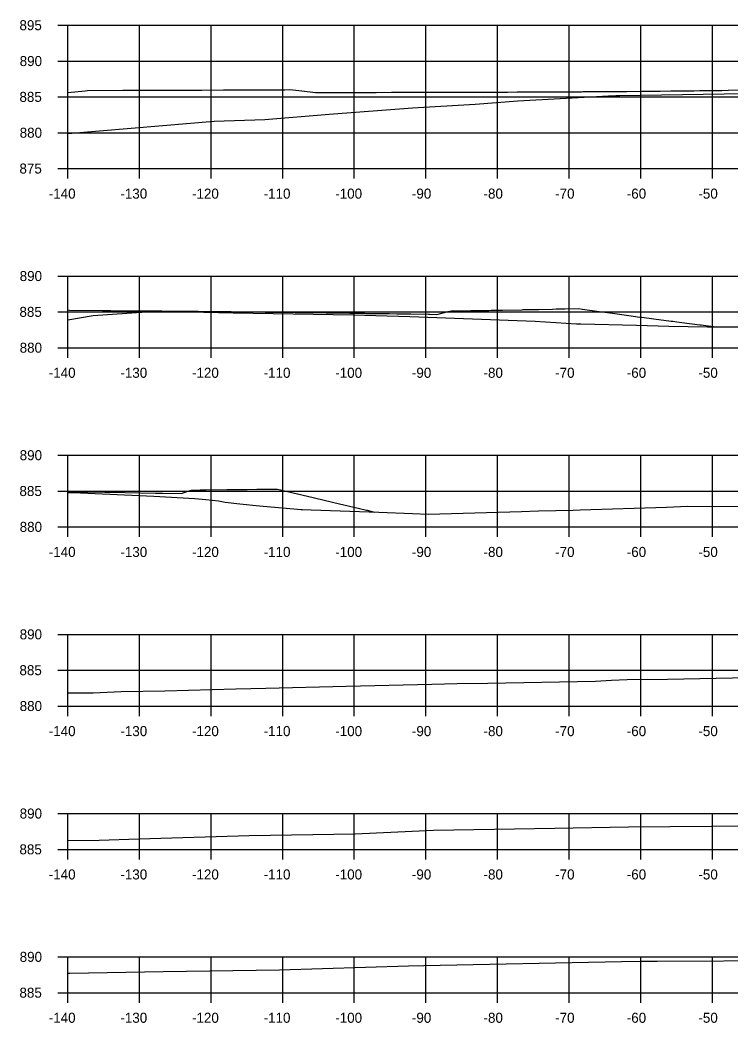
# Model space of a CAD drawing. Extents: x 1098669 to 1198896, y 698679 to 704410.
# Drawn here: x 1110634.5 to 1110733.7, y 701504.9 to 701644.8 of the extents above; entities that cross this region are included whole.
import ezdxf

# ---------------------------------------------------------------- set-up
doc = ezdxf.new("R2010")
doc.units = 0
for name, color, linetype in [('Proposed Surface', 7, 'Continuous'), ('R_Axis', 7, 'Continuous'), ('R_Axis Annot', 7, 'Continuous'), ('R_Fin Surface', 7, 'Continuous'), ('R_Grid', 7, 'Continuous')]:
    doc.layers.add(name, color=color, linetype=linetype)

msp = doc.modelspace()

# ---------------------------------------------------------------- linework, layer by layer
at = {"layer": 'Proposed Surface'}
for points in [[(1110641.16, 701629), (1110654.45, 701630.12), (1110661.6, 701630.72), (1110668.68, 701630.97), (1110677.65, 701631.7), (1110689.27, 701632.59), (1110698.01, 701633.13), (1110703.97, 701633.57), (1110716.65, 701634.28), (1110717.65, 701634.31), (1110718.25, 701634.32), (1110732.78, 701634.57), (1110735.56, 701634.61)], [(1110641.16, 701603), (1110644.68, 701603.63), (1110650.75, 701604.02), (1110652.23, 701604.13), (1110654.28, 701604.13), (1110658.11, 701604.13), (1110664.23, 701603.99), (1110681.01, 701603.73), (1110688.9, 701603.47), (1110706.39, 701602.82), (1110712.18, 701602.47), (1110712.61, 701602.46), (1110712.8, 701602.45), (1110720.56, 701602.28), (1110725.07, 701602.12), (1110730.48, 701602.06), (1110735.69, 701602.04)], [(1110641.16, 701578.92), (1110641.93, 701578.91), (1110653.19, 701578.39), (1110658.89, 701578.1), (1110660.41, 701577.95), (1110662.19, 701577.78), (1110663.15, 701577.57), (1110665.18, 701577.35), (1110667.93, 701577.08), (1110673.23, 701576.61), (1110673.75, 701576.56), (1110673.94, 701576.54), (1110675.13, 701576.5), (1110684.6, 701576.18), (1110689.29, 701576), (1110691.47, 701575.91), (1110704.51, 701576.28), (1110706.89, 701576.36), (1110711.72, 701576.47), (1110712.68, 701576.52), (1110724.75, 701576.87), (1110727.68, 701577.01), (1110734.95, 701576.99)], [(1110641.16, 701550.96), (1110644.68, 701550.98), (1110648.59, 701551.14), (1110654.71, 701551.25), (1110664.63, 701551.51), (1110668.83, 701551.61), (1110680.01, 701551.89), (1110691.99, 701552.16), (1110695.53, 701552.25), (1110699.79, 701552.34), (1110714.81, 701552.62), (1110717.08, 701552.73), (1110719.23, 701552.83), (1110724.88, 701552.88), (1110756.59, 701553.51)], [(1110641.16, 701530.35), (1110645.55, 701530.42), (1110651.09, 701530.58), (1110666.49, 701531.04), (1110681.3, 701531.28), (1110692.21, 701531.8), (1110709.14, 701532.09), (1110719.46, 701532.28), (1110754.17, 701532.55)], [(1110641.16, 701511.83), (1110641.46, 701511.83), (1110654.46, 701512.1), (1110670.71, 701512.33), (1110688.72, 701512.87), (1110690.88, 701512.93), (1110718.45, 701513.47), (1110721.18, 701513.52), (1110723.44, 701513.53), (1110760.56, 701513.71)]]:
    msp.add_lwpolyline(points, dxfattribs=at)
at = {"layer": 'R_Axis'}
for p, q in [((1110639.76, 701644.13), (1110641.16, 701644.13)), ((1110641.16, 701624.13), (1110641.16, 701644.13)), ((1110639.76, 701639.13), (1110641.16, 701639.13)), ((1110639.76, 701634.13), (1110641.16, 701634.13)), ((1110639.76, 701629.13), (1110641.16, 701629.13)), ((1110639.76, 701624.13), (1110641.16, 701624.13)), ((1110641.16, 701624.13), (1110921.16, 701624.13)), ((1110641.16, 701622.73), (1110641.16, 701624.13)), ((1110651.16, 701622.73), (1110651.16, 701624.13)), ((1110661.16, 701622.73), (1110661.16, 701624.13)), ((1110671.16, 701622.73), (1110671.16, 701624.13)), ((1110681.16, 701622.73), (1110681.16, 701624.13)), ((1110691.16, 701622.73), (1110691.16, 701624.13)), ((1110701.16, 701622.73), (1110701.16, 701624.13)), ((1110711.16, 701622.73), (1110711.16, 701624.13)), ((1110721.16, 701622.73), (1110721.16, 701624.13)), ((1110731.16, 701622.73), (1110731.16, 701624.13)), ((1110639.76, 701609.13), (1110641.16, 701609.13)), ((1110641.16, 701599.13), (1110641.16, 701609.13)), ((1110639.76, 701604.13), (1110641.16, 701604.13)), ((1110639.76, 701599.13), (1110641.16, 701599.13)), ((1110641.16, 701599.13), (1110921.16, 701599.13)), ((1110641.16, 701597.73), (1110641.16, 701599.13)), ((1110651.16, 701597.73), (1110651.16, 701599.13)), ((1110661.16, 701597.73), (1110661.16, 701599.13)), ((1110671.16, 701597.73), (1110671.16, 701599.13)), ((1110681.16, 701597.73), (1110681.16, 701599.13)), ((1110691.16, 701597.73), (1110691.16, 701599.13)), ((1110701.16, 701597.73), (1110701.16, 701599.13)), ((1110711.16, 701597.73), (1110711.16, 701599.13)), ((1110721.16, 701597.73), (1110721.16, 701599.13)), ((1110731.16, 701597.73), (1110731.16, 701599.13)), ((1110639.76, 701584.13), (1110641.16, 701584.13)), ((1110641.16, 701574.13), (1110641.16, 701584.13)), ((1110639.76, 701579.13), (1110641.16, 701579.13)), ((1110639.76, 701574.13), (1110641.16, 701574.13)), ((1110641.16, 701574.13), (1110921.16, 701574.13)), ((1110641.16, 701572.73), (1110641.16, 701574.13)), ((1110651.16, 701572.73), (1110651.16, 701574.13)), ((1110661.16, 701572.73), (1110661.16, 701574.13)), ((1110671.16, 701572.73), (1110671.16, 701574.13)), ((1110681.16, 701572.73), (1110681.16, 701574.13)), ((1110691.16, 701572.73), (1110691.16, 701574.13)), ((1110701.16, 701572.73), (1110701.16, 701574.13)), ((1110711.16, 701572.73), (1110711.16, 701574.13)), ((1110721.16, 701572.73), (1110721.16, 701574.13)), ((1110731.16, 701572.73), (1110731.16, 701574.13)), ((1110639.76, 701559.13), (1110641.16, 701559.13)), ((1110641.16, 701549.13), (1110641.16, 701559.13)), ((1110639.76, 701554.13), (1110641.16, 701554.13)), ((1110639.76, 701549.13), (1110641.16, 701549.13)), ((1110641.16, 701549.13), (1110921.16, 701549.13)), ((1110641.16, 701547.73), (1110641.16, 701549.13)), ((1110651.16, 701547.73), (1110651.16, 701549.13)), ((1110661.16, 701547.73), (1110661.16, 701549.13)), ((1110671.16, 701547.73), (1110671.16, 701549.13)), ((1110681.16, 701547.73), (1110681.16, 701549.13)), ((1110691.16, 701547.73), (1110691.16, 701549.13)), ((1110701.16, 701547.73), (1110701.16, 701549.13)), ((1110711.16, 701547.73), (1110711.16, 701549.13)), ((1110721.16, 701547.73), (1110721.16, 701549.13)), ((1110731.16, 701547.73), (1110731.16, 701549.13)), ((1110639.76, 701534.13), (1110641.16, 701534.13)), ((1110641.16, 701529.13), (1110641.16, 701534.13)), ((1110639.76, 701529.13), (1110641.16, 701529.13)), ((1110641.16, 701529.13), (1110921.16, 701529.13)), ((1110641.16, 701527.73), (1110641.16, 701529.13)), ((1110651.16, 701527.73), (1110651.16, 701529.13)), ((1110661.16, 701527.73), (1110661.16, 701529.13)), ((1110671.16, 701527.73), (1110671.16, 701529.13)), ((1110681.16, 701527.73), (1110681.16, 701529.13)), ((1110691.16, 701527.73), (1110691.16, 701529.13)), ((1110701.16, 701527.73), (1110701.16, 701529.13)), ((1110711.16, 701527.73), (1110711.16, 701529.13)), ((1110721.16, 701527.73), (1110721.16, 701529.13)), ((1110731.16, 701527.73), (1110731.16, 701529.13)), ((1110639.76, 701514.13), (1110641.16, 701514.13)), ((1110641.16, 701509.13), (1110641.16, 701514.13)), ((1110639.76, 701509.13), (1110641.16, 701509.13)), ((1110641.16, 701509.13), (1110921.16, 701509.13)), ((1110641.16, 701507.73), (1110641.16, 701509.13)), ((1110651.16, 701507.73), (1110651.16, 701509.13)), ((1110661.16, 701507.73), (1110661.16, 701509.13)), ((1110671.16, 701507.73), (1110671.16, 701509.13)), ((1110681.16, 701507.73), (1110681.16, 701509.13)), ((1110691.16, 701507.73), (1110691.16, 701509.13)), ((1110701.16, 701507.73), (1110701.16, 701509.13)), ((1110711.16, 701507.73), (1110711.16, 701509.13)), ((1110721.16, 701507.73), (1110721.16, 701509.13)), ((1110731.16, 701507.73), (1110731.16, 701509.13))]:
    msp.add_line(p, q, dxfattribs=at)
at = {"layer": 'R_Fin Surface'}
for points in [[(1110641.16, 701634.72), (1110643.57, 701634.99), (1110643.59, 701634.99), (1110643.59, 701634.99), (1110643.9, 701635.03), (1110648.85, 701635.05), (1110649.16, 701635.05), (1110649.77, 701635.05), (1110651.93, 701635.05), (1110654.17, 701635.06), (1110654.29, 701635.06), (1110654.35, 701635.06), (1110658.09, 701635.07), (1110658.54, 701635.08), (1110659.86, 701635.08), (1110659.86, 701635.08), (1110659.86, 701635.08), (1110659.86, 701635.08), (1110662.88, 701635.09), (1110664.28, 701635.09), (1110665.33, 701635.1), (1110666.07, 701635.1), (1110667.19, 701635.11), (1110667.98, 701635.11), (1110670.34, 701635.12), (1110670.75, 701635.12), (1110671.03, 701635.13), (1110671.48, 701635.13), (1110672.18, 701635.14), (1110673.85, 701634.95), (1110675.74, 701634.74), (1110675.76, 701634.74), (1110675.93, 701634.72), (1110676.14, 701634.72), (1110679.72, 701634.74), (1110679.98, 701634.74), (1110681.34, 701634.74), (1110681.48, 701634.74), (1110681.76, 701634.74), (1110684.2, 701634.76), (1110686.33, 701634.77), (1110686.79, 701634.77), (1110687.1, 701634.77), (1110688.39, 701634.78), (1110688.83, 701634.78), (1110690.37, 701634.78), (1110691.62, 701634.78), (1110692.07, 701634.78), (1110692.43, 701634.78), (1110692.57, 701634.78), (1110695.38, 701634.79), (1110696.72, 701634.79), (1110696.93, 701634.79), (1110697.32, 701634.79), (1110698.64, 701634.79), (1110700.86, 701634.8), (1110701.56, 701634.8), (1110702.54, 701634.8), (1110703.89, 701634.81), (1110704.98, 701634.81), (1110706.3, 701634.82), (1110707.73, 701634.83), (1110708.42, 701634.83), (1110709.09, 701634.83), (1110710.84, 701634.84), (1110712.9, 701634.85), (1110713.05, 701634.86), (1110713.17, 701634.86), (1110715.61, 701634.87), (1110717.25, 701634.89), (1110717.74, 701634.89), (1110718.04, 701634.89), (1110719.21, 701634.9), (1110721.31, 701634.92), (1110722.57, 701634.93), (1110723.16, 701634.94), (1110723.84, 701634.94), (1110725.35, 701634.96), (1110726.18, 701634.97), (1110728.26, 701634.99), (1110728.56, 701634.99), (1110729.39, 701635), (1110732.46, 701635.04), (1110733.35, 701635.05), (1110733.36, 701635.05), (1110733.41, 701635.05), (1110736.68, 701635.09)], [(1110641.16, 701604.41), (1110641.39, 701604.35), (1110646, 701604.32), (1110647.15, 701604.31), (1110649.05, 701604.29), (1110653.24, 701604.27), (1110653.78, 701604.27), (1110654.31, 701604.26), (1110657.47, 701604.23), (1110659.18, 701604.22), (1110659.24, 701604.22), (1110659.38, 701604.22), (1110663.5, 701604.17), (1110663.99, 701604.17), (1110665.4, 701604.15), (1110665.44, 701604.15), (1110665.51, 701604.15), (1110666.09, 701604.14), (1110668.73, 701604.11), (1110669.03, 701604.1), (1110671.39, 701604.07), (1110672.89, 701604.05), (1110673.41, 701604.04), (1110674.65, 701604.02), (1110677.24, 701603.99), (1110677.68, 701603.98), (1110678.03, 701603.98), (1110680.52, 701603.95), (1110682.58, 701603.93), (1110682.74, 701603.92), (1110683, 701603.92), (1110686.09, 701603.88), (1110687.09, 701603.87), (1110687.4, 701603.86), (1110688.68, 701603.84), (1110689.06, 701603.84), (1110691.54, 701603.8), (1110691.64, 701603.8), (1110692.7, 701603.78), (1110694.26, 701604.17), (1110694.7, 701604.27), (1110695.37, 701604.28), (1110695.71, 701604.28), (1110695.89, 701604.28), (1110695.93, 701604.28), (1110697.42, 701604.3), (1110697.99, 701604.31), (1110698.92, 701604.32), (1110699.77, 701604.34), (1110699.93, 701604.34), (1110700.28, 701604.35), (1110700.93, 701604.36), (1110701.86, 701604.38), (1110704.58, 701604.43), (1110704.75, 701604.44), (1110705.19, 701604.44), (1110706.94, 701604.48), (1110708.83, 701604.52), (1110709.33, 701604.53), (1110710.54, 701604.55), (1110712.48, 701604.59), (1110712.96, 701604.52), (1110713.03, 701604.51), (1110715.35, 701604.19), (1110715.82, 701604.12), (1110716.84, 701603.98), (1110717.19, 701603.93), (1110719.49, 701603.62), (1110721.03, 701603.41), (1110721.17, 701603.39), (1110721.31, 701603.38), (1110722.99, 701603.15), (1110725.39, 701602.84), (1110725.61, 701602.81), (1110726.18, 701602.74), (1110726.89, 701602.65), (1110729.42, 701602.33), (1110729.59, 701602.3), (1110731.26, 701602.1), (1110731.29, 701602.09), (1110731.57, 701602.06)], [(1110641.16, 701579.04), (1110646.35, 701578.96), (1110649.15, 701578.92), (1110653.42, 701578.85), (1110654.36, 701578.84), (1110657.01, 701578.79), (1110657.91, 701579.1), (1110658.42, 701579.27), (1110658.61, 701579.27), (1110659.13, 701579.27), (1110659.64, 701579.28), (1110660.49, 701579.29), (1110663.37, 701579.33), (1110665.27, 701579.35), (1110666.18, 701579.36), (1110667.56, 701579.37), (1110669, 701579.39), (1110670.44, 701579.4), (1110674.63, 701578.41), (1110679.11, 701577.35), (1110681.7, 701576.73), (1110682.84, 701576.47), (1110682.94, 701576.44), (1110683.96, 701576.2)]]:
    msp.add_lwpolyline(points, dxfattribs=at)
at = {"layer": 'R_Grid'}
for p, q in [((1110641.16, 701644.13), (1110921.16, 701644.13)), ((1110641.16, 701624.13), (1110641.16, 701644.13)), ((1110651.16, 701624.13), (1110651.16, 701644.13)), ((1110661.16, 701624.13), (1110661.16, 701644.13)), ((1110671.16, 701624.13), (1110671.16, 701644.13)), ((1110681.16, 701624.13), (1110681.16, 701644.13)), ((1110691.16, 701624.13), (1110691.16, 701644.13)), ((1110701.16, 701624.13), (1110701.16, 701644.13)), ((1110711.16, 701624.13), (1110711.16, 701644.13)), ((1110721.16, 701624.13), (1110721.16, 701644.13)), ((1110731.16, 701624.13), (1110731.16, 701644.13)), ((1110641.16, 701639.13), (1110921.16, 701639.13)), ((1110641.16, 701634.13), (1110921.16, 701634.13)), ((1110641.16, 701629.13), (1110921.16, 701629.13)), ((1110641.16, 701624.13), (1110921.16, 701624.13)), ((1110641.16, 701609.13), (1110921.16, 701609.13)), ((1110641.16, 701599.13), (1110641.16, 701609.13)), ((1110651.16, 701599.13), (1110651.16, 701609.13)), ((1110661.16, 701599.13), (1110661.16, 701609.13)), ((1110671.16, 701599.13), (1110671.16, 701609.13)), ((1110681.16, 701599.13), (1110681.16, 701609.13)), ((1110691.16, 701599.13), (1110691.16, 701609.13)), ((1110701.16, 701599.13), (1110701.16, 701609.13)), ((1110711.16, 701599.13), (1110711.16, 701609.13)), ((1110721.16, 701599.13), (1110721.16, 701609.13)), ((1110731.16, 701599.13), (1110731.16, 701609.13)), ((1110641.16, 701604.13), (1110921.16, 701604.13)), ((1110641.16, 701599.13), (1110921.16, 701599.13)), ((1110641.16, 701584.13), (1110921.16, 701584.13)), ((1110641.16, 701574.13), (1110641.16, 701584.13)), ((1110651.16, 701574.13), (1110651.16, 701584.13)), ((1110661.16, 701574.13), (1110661.16, 701584.13)), ((1110671.16, 701574.13), (1110671.16, 701584.13)), ((1110681.16, 701574.13), (1110681.16, 701584.13)), ((1110691.16, 701574.13), (1110691.16, 701584.13)), ((1110701.16, 701574.13), (1110701.16, 701584.13)), ((1110711.16, 701574.13), (1110711.16, 701584.13)), ((1110721.16, 701574.13), (1110721.16, 701584.13)), ((1110731.16, 701574.13), (1110731.16, 701584.13)), ((1110641.16, 701579.13), (1110921.16, 701579.13)), ((1110641.16, 701574.13), (1110921.16, 701574.13)), ((1110641.16, 701559.13), (1110921.16, 701559.13)), ((1110641.16, 701549.13), (1110641.16, 701559.13)), ((1110651.16, 701549.13), (1110651.16, 701559.13)), ((1110661.16, 701549.13), (1110661.16, 701559.13)), ((1110671.16, 701549.13), (1110671.16, 701559.13)), ((1110681.16, 701549.13), (1110681.16, 701559.13)), ((1110691.16, 701549.13), (1110691.16, 701559.13)), ((1110701.16, 701549.13), (1110701.16, 701559.13)), ((1110711.16, 701549.13), (1110711.16, 701559.13)), ((1110721.16, 701549.13), (1110721.16, 701559.13)), ((1110731.16, 701549.13), (1110731.16, 701559.13)), ((1110641.16, 701554.13), (1110921.16, 701554.13)), ((1110641.16, 701549.13), (1110921.16, 701549.13)), ((1110641.16, 701534.13), (1110921.16, 701534.13)), ((1110641.16, 701529.13), (1110641.16, 701534.13)), ((1110651.16, 701529.13), (1110651.16, 701534.13)), ((1110661.16, 701529.13), (1110661.16, 701534.13)), ((1110671.16, 701529.13), (1110671.16, 701534.13)), ((1110681.16, 701529.13), (1110681.16, 701534.13)), ((1110691.16, 701529.13), (1110691.16, 701534.13)), ((1110701.16, 701529.13), (1110701.16, 701534.13)), ((1110711.16, 701529.13), (1110711.16, 701534.13)), ((1110721.16, 701529.13), (1110721.16, 701534.13)), ((1110731.16, 701529.13), (1110731.16, 701534.13)), ((1110641.16, 701529.13), (1110921.16, 701529.13)), ((1110641.16, 701514.13), (1110921.16, 701514.13)), ((1110641.16, 701509.13), (1110641.16, 701514.13)), ((1110651.16, 701509.13), (1110651.16, 701514.13)), ((1110661.16, 701509.13), (1110661.16, 701514.13)), ((1110671.16, 701509.13), (1110671.16, 701514.13)), ((1110681.16, 701509.13), (1110681.16, 701514.13)), ((1110691.16, 701509.13), (1110691.16, 701514.13)), ((1110701.16, 701509.13), (1110701.16, 701514.13)), ((1110711.16, 701509.13), (1110711.16, 701514.13)), ((1110721.16, 701509.13), (1110721.16, 701514.13)), ((1110731.16, 701509.13), (1110731.16, 701514.13)), ((1110641.16, 701509.13), (1110921.16, 701509.13))]:
    msp.add_line(p, q, dxfattribs=at)

# ---------------------------------------------------------------- texts
at = {"layer": 'R_Axis Annot'}
for s, p in [('895', (1110634.41, 701643.43)), ('890', (1110634.44, 701638.43)), ('885', (1110634.41, 701633.43)), ('880', (1110634.44, 701628.43)), ('875', (1110634.41, 701623.43)), ('-140', (1110638.5, 701619.93)), ('-130', (1110648.5, 701619.93)), ('-120', (1110658.5, 701619.93)), ('-110', (1110668.5, 701619.93)), ('-100', (1110678.5, 701619.93)), ('-90', (1110689.2, 701619.93)), ('-80', (1110699.2, 701619.93)), ('-70', (1110709.2, 701619.93)), ('-60', (1110719.2, 701619.93)), ('-50', (1110729.2, 701619.93)), ('890', (1110634.44, 701608.43)), ('885', (1110634.41, 701603.43)), ('880', (1110634.44, 701598.43)), ('-140', (1110638.5, 701594.93)), ('-130', (1110648.5, 701594.93)), ('-120', (1110658.5, 701594.93)), ('-110', (1110668.5, 701594.93)), ('-100', (1110678.5, 701594.93)), ('-90', (1110689.2, 701594.93)), ('-80', (1110699.2, 701594.93)), ('-70', (1110709.2, 701594.93)), ('-60', (1110719.2, 701594.93)), ('-50', (1110729.2, 701594.93)), ('890', (1110634.44, 701583.43)), ('885', (1110634.41, 701578.43)), ('880', (1110634.44, 701573.43)), ('-140', (1110638.5, 701569.93)), ('-130', (1110648.5, 701569.93)), ('-120', (1110658.5, 701569.93)), ('-110', (1110668.5, 701569.93)), ('-100', (1110678.5, 701569.93)), ('-90', (1110689.2, 701569.93)), ('-80', (1110699.2, 701569.93)), ('-70', (1110709.2, 701569.93)), ('-60', (1110719.2, 701569.93)), ('-50', (1110729.2, 701569.93)), ('890', (1110634.44, 701558.43)), ('885', (1110634.41, 701553.43)), ('880', (1110634.44, 701548.43)), ('-140', (1110638.5, 701544.93)), ('-130', (1110648.5, 701544.93)), ('-120', (1110658.5, 701544.93)), ('-110', (1110668.5, 701544.93)), ('-100', (1110678.5, 701544.93)), ('-90', (1110689.2, 701544.93)), ('-80', (1110699.2, 701544.93)), ('-70', (1110709.2, 701544.93)), ('-60', (1110719.2, 701544.93)), ('-50', (1110729.2, 701544.93)), ('890', (1110634.44, 701533.43)), ('885', (1110634.41, 701528.43)), ('-140', (1110638.5, 701524.93)), ('-130', (1110648.5, 701524.93)), ('-120', (1110658.5, 701524.93)), ('-110', (1110668.5, 701524.93)), ('-100', (1110678.5, 701524.93)), ('-90', (1110689.2, 701524.93)), ('-80', (1110699.2, 701524.93)), ('-70', (1110709.2, 701524.93)), ('-60', (1110719.2, 701524.93)), ('-50', (1110729.2, 701524.93)), ('890', (1110634.44, 701513.43)), ('885', (1110634.41, 701508.43)), ('-140', (1110638.5, 701504.93)), ('-130', (1110648.5, 701504.93)), ('-120', (1110658.5, 701504.93)), ('-110', (1110668.5, 701504.93)), ('-100', (1110678.5, 701504.93)), ('-90', (1110689.2, 701504.93)), ('-80', (1110699.2, 701504.93)), ('-70', (1110709.2, 701504.93)), ('-60', (1110719.2, 701504.93)), ('-50', (1110729.2, 701504.93))]:
    msp.add_text(s, height=1.4, dxfattribs=at).set_placement(p)

doc.saveas('drawing.dxf')
